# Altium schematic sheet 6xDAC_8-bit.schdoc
size 420 x 297 mm; Symbol: Drawing-Symbol_A4; @Project Name: Inverted_MAML_6x6; @Page Count: 1; @Update Date: 2026-06-15; @Create Date: 2026-06-15; @Schematic Name: Schematic1; @Page No: 1; @Page Name: P1; Company: EasyEDA.com; Version: V1.0; Page Size: A4; Device: Drawing-Symbol_A4; @Create Time: 21:23:07; @Update Time: 21:23:07; Border: 1; Width: 1655; Height: 1170; Region Start: 1; X Region Count: 6; Y Region Count: 4; Blade Width: 10; Title Block Position: 3
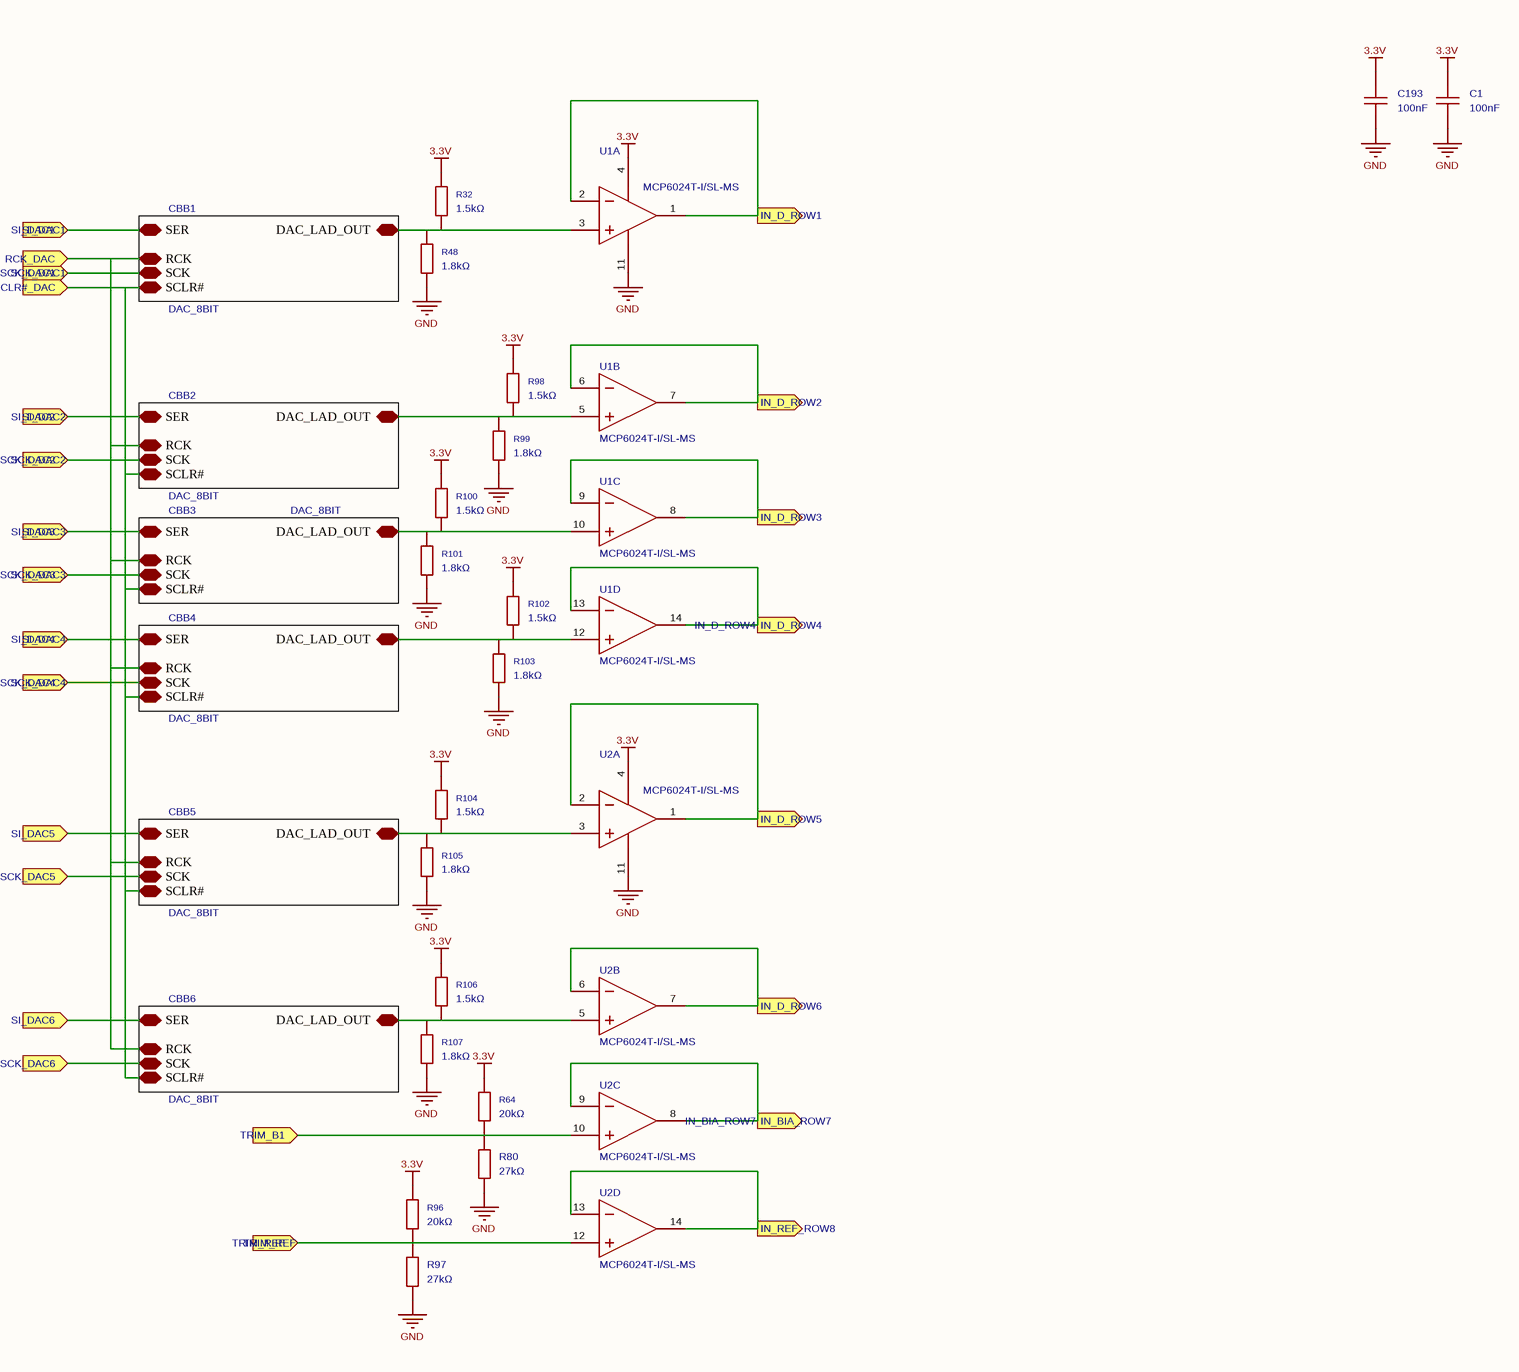
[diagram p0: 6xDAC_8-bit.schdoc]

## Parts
C1  100nF  [C0402]
C193  100nF  [C0402]
R32  1.5kΩ  [R0402]
R48  1.8kΩ  [R0402]
R64  20kΩ  [R0402]
R80  27kΩ  [R0402]
R96  20kΩ  [R0402]
R97  27kΩ  [R0402]
R98  1.5kΩ  [R0402]
R99  1.8kΩ  [R0402]
R100  1.5kΩ  [R0402]
R101  1.8kΩ  [R0402]
R102  1.5kΩ  [R0402]
R103  1.8kΩ  [R0402]
R104  1.5kΩ  [R0402]
R105  1.8kΩ  [R0402]
R106  1.5kΩ  [R0402]
R107  1.8kΩ  [R0402]
U1  MCP6024T-I/SL-MS  [SOIC-14_L8.7-W3.9-P1.27-LS6.0-BL-1]  (parts A,B,C,D of 4)
U2  MCP6024T-I/SL-MS  [SOIC-14_L8.7-W3.9-P1.27-LS6.0-BL-1]  (parts A,B,C,D of 4)

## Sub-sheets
CBB1 = DAC_8B_R_2R.schdoc: SER, RCK, SCK, SCLR#, DAC_LAD_OUT  | Symbol: DAC_8BIT
CBB2 = DAC_8B_R_2R.schdoc: SER, RCK, SCK, SCLR#, DAC_LAD_OUT  | Symbol: DAC_8BIT
CBB3 = DAC_8B_R_2R.schdoc: SER, RCK, SCK, SCLR#, DAC_LAD_OUT  | Symbol: DAC_8BIT
CBB4 = DAC_8B_R_2R.schdoc: SER, RCK, SCK, SCLR#, DAC_LAD_OUT  | Symbol: DAC_8BIT
CBB5 = DAC_8B_R_2R.schdoc: SER, RCK, SCK, SCLR#, DAC_LAD_OUT  | Symbol: DAC_8BIT
CBB6 = DAC_8B_R_2R.schdoc: SER, RCK, SCK, SCLR#, DAC_LAD_OUT  | Symbol: DAC_8BIT

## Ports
IN_BIA_ROW7 (out), IN_D_ROW1 (out), IN_D_ROW2 (out), IN_D_ROW3 (out), IN_D_ROW4 (out), IN_D_ROW5 (out), IN_D_ROW6 (out), IN_REF_ROW8 (out), RCK_DAC (in), SCK_DAC1 (in), SCK_DAC2 (in), SCK_DAC3 (in), SCK_DAC4 (in), SCK_DAC5 (in), SCK_DAC6 (in), SCLR#_DAC (in), SI_DAC1 (in), SI_DAC2 (in), SI_DAC3 (in), SI_DAC4 (in), SI_DAC5 (in), SI_DAC6 (in), TRIM_B1 (in), TRIM_REF (in)

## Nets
3.3V: C1.2 C193.2 R32.2 R64.2 R96.2 R98.2 R100.2 R102.2 R104.2 R106.2 U1.4(V+) U2.4(V+)
GND: C1.1 C193.1 R48.1 R80.1 R97.1 R99.1 R101.1 R103.1 R105.1 R107.1 U1.11(V-) U2.11(V-)
IN_BIA_ROW7: U2.8(OUT3) U2.9(IN3-) ; port IN_BIA_ROW7
IN_D_ROW1: U1.1(OUT1) U1.2(IN1-) ; port IN_D_ROW1
IN_D_ROW2: U1.6(IN2-) U1.7(OUT2) ; port IN_D_ROW2
IN_D_ROW3: U1.8(OUT3) U1.9(IN3-) ; port IN_D_ROW3
IN_D_ROW4: U1.13(IN4-) U1.14(OUT4) ; port IN_D_ROW4
IN_D_ROW5: U2.1(OUT1) U2.2(IN1-) ; port IN_D_ROW5
IN_D_ROW6: U2.6(IN2-) U2.7(OUT2) ; port IN_D_ROW6
IN_REF_ROW8: U2.13(IN4-) U2.14(OUT4) ; port IN_REF_ROW8
RCK_DAC: port RCK_DAC, sheet CBB1/RCK, sheet CBB2/RCK, sheet CBB3/RCK, sheet CBB4/RCK, sheet CBB5/RCK, sheet CBB6/RCK
SCK_DAC1: port SCK_DAC1, sheet CBB1/SCK
SCK_DAC2: port SCK_DAC2, sheet CBB2/SCK
SCK_DAC3: port SCK_DAC3, sheet CBB3/SCK
SCK_DAC4: port SCK_DAC4, sheet CBB4/SCK
SCK_DAC5: port SCK_DAC5, sheet CBB5/SCK
SCK_DAC6: port SCK_DAC6, sheet CBB6/SCK
SCLR#_DAC: port SCLR#_DAC, sheet CBB1/SCLR#, sheet CBB2/SCLR#, sheet CBB3/SCLR#, sheet CBB4/SCLR#, sheet CBB5/SCLR#, sheet CBB6/SCLR#
SI_DAC1: port SI_DAC1, sheet CBB1/SER
SI_DAC2: port SI_DAC2, sheet CBB2/SER
SI_DAC3: port SI_DAC3, sheet CBB3/SER
SI_DAC4: port SI_DAC4, sheet CBB4/SER
SI_DAC5: port SI_DAC5, sheet CBB5/SER
SI_DAC6: port SI_DAC6, sheet CBB6/SER
TRIM_B1: R64.1 R80.2 U2.10(IN3+) ; port TRIM_B1
TRIM_REF: R96.1 R97.2 U2.12(IN4+) ; port TRIM_REF
NetR32_1: R32.1 R48.2 U1.3(IN1+) ; sheet CBB1/DAC_LAD_OUT
NetR98_1: R98.1 R99.2 U1.5(IN2+) ; sheet CBB2/DAC_LAD_OUT
NetR100_1: R100.1 R101.2 U1.10(IN3+) ; sheet CBB3/DAC_LAD_OUT
NetR102_1: R102.1 R103.2 U1.12(IN4+) ; sheet CBB4/DAC_LAD_OUT
NetR104_1: R104.1 R105.2 U2.3(IN1+) ; sheet CBB5/DAC_LAD_OUT
NetR106_1: R106.1 R107.2 U2.5(IN2+) ; sheet CBB6/DAC_LAD_OUT

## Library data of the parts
C1 C193 = CL05B104KO5NNNC: Capacitance:100nF Tolerance:±10% Tolerance:±10% Voltage Rating:16V Temperature Coefficient:X7R; Manufacturer: SAMSUNG(三星); 3D Model: b7d13df3e9464d7a99d0651d1a5b4d570819f05c4eef4c71ace90d822a990e87; 3D Model Transform: 39.37,19.685,0,0,0,0,0,0,0; Tolerance: ±10%; Voltage Rating: 16V; Temperature Coefficient: X7R; AddInBom: yes; ModelName: C0402_L1.0-W0.5-H0.5
R32 R98 R100 R102 R104 R106 = 0402WGF1501TCE: Type:Thick Film Resistors Resistance:1.5kΩ Tolerance:±1% Tolerance:±1% Power(Watts): Overload Voltage (Max): Temperature Coefficient:±100ppm/℃ Temperature Coefficient:±100ppm/℃ Operating Temperature Range:-55℃~+155℃ Operating Temperature Range:-55℃~+155℃; Manufacturer: UNI-ROYAL(厚声); AddInBom: yes; ModelId: efdecb7dae4442949d28eecaf748420f0819f05c4eef4c71ace90d822a990e87; ModelName: R0402_L1.0-W0.5-H0.4; ModelTransform: 39.37,19.685,0,0,0,0,0,0,0; Tolerance: ±1%
R48 R99 R101 R103 R105 R107 = 0402WGF1801TCE: Type:Thick Film Resistor Resistance:1.8kΩ Tolerance:±1% Tolerance:±1% Power(Watts):62.5mW Voltage-Supply(Max):50V Temperature Coefficient:±100ppm/℃ Temperature Coefficient:±100ppm/℃ Operating Temperature:-55℃~+155℃ Operating Temperature:-55℃~+155℃; Manufacturer: UNI-ROYAL(厚声); AddInBom: yes; ModelId: efdecb7dae4442949d28eecaf748420f0819f05c4eef4c71ace90d822a990e87; ModelName: R0402_L1.0-W0.5-H0.4; ModelTransform: 39.37,19.685,0,0,0,0,0,0,0; Tolerance: ±1%; Power(Watts): 62.5mW; Voltage-Supply(Max): 50V
R64 R96 = 0402WGF2002TCE: Type:Thick Film Resistors Resistance:20kΩ Tolerance:±1% Tolerance:±1% Power(Watts): Overload Voltage (Max): Temperature Coefficient:±100ppm/℃ Temperature Coefficient:±100ppm/℃ Operating Temperature Range:-55℃~+155℃ Operating Temperature Range:-55℃~+155℃; Manufacturer: UNI-ROYAL(厚声); AddInBom: yes; ModelId: efdecb7dae4442949d28eecaf748420f0819f05c4eef4c71ace90d822a990e87; ModelName: R0402_L1.0-W0.5-H0.4; ModelTransform: 39.37,19.685,0,0,0,0,0,0,0; Tolerance: ±1%
R80 R97 = 0402WGF2702TCE: Type:Thick Film Resistor Resistance:27kΩ Tolerance:±1% Tolerance:±1% Power(Watts):62.5mW Voltage-Supply(Max):50V Temperature Coefficient:±100ppm/℃ Temperature Coefficient:±100ppm/℃ Operating Temperature:-55℃~+155℃ Operating Temperature:-55℃~+155℃; Manufacturer: UNI-ROYAL(厚声); AddInBom: yes; ModelId: efdecb7dae4442949d28eecaf748420f0819f05c4eef4c71ace90d822a990e87; ModelName: R0402_L1.0-W0.5-H0.4; ModelTransform: 39.37,19.685,0,0,0,0,0,0,0; Tolerance: ±1%; Power(Watts): 62.5mW; Voltage-Supply(Max): 50V
U1 U2 = MCP6024T-I/SL-MS: Manufacturer: MSKSEMI(美森科); Relevance: []; AddInBom: yes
